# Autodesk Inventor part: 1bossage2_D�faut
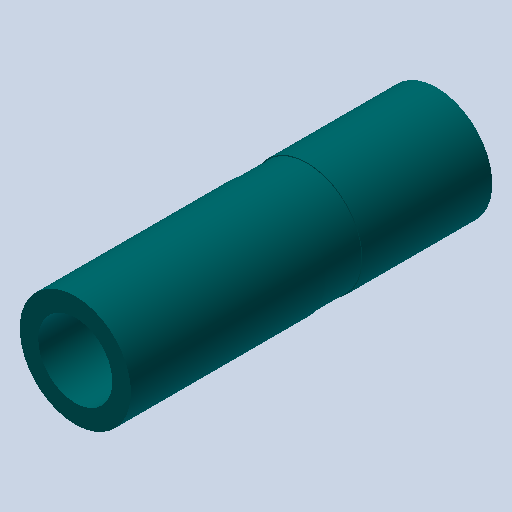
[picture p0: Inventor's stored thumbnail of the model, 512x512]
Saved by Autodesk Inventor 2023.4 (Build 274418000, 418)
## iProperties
Created: 2011-01
Part Number: 1bossage2_D�faut
Document SubType Name: Modeling
Designer: eric
Density: 1 g/cm^3
Mass: 2.43549 g
Surface Area: 25.8107 cm^2
Volume: 2.43549 cm^3
Material: Générique
Appearance: 0,128,128_1
Author: eric
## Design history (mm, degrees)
feature "Base1"
node "Corps solides"
node "Corps surfaciques"
node "Solide1"
